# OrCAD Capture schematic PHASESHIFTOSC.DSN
size A
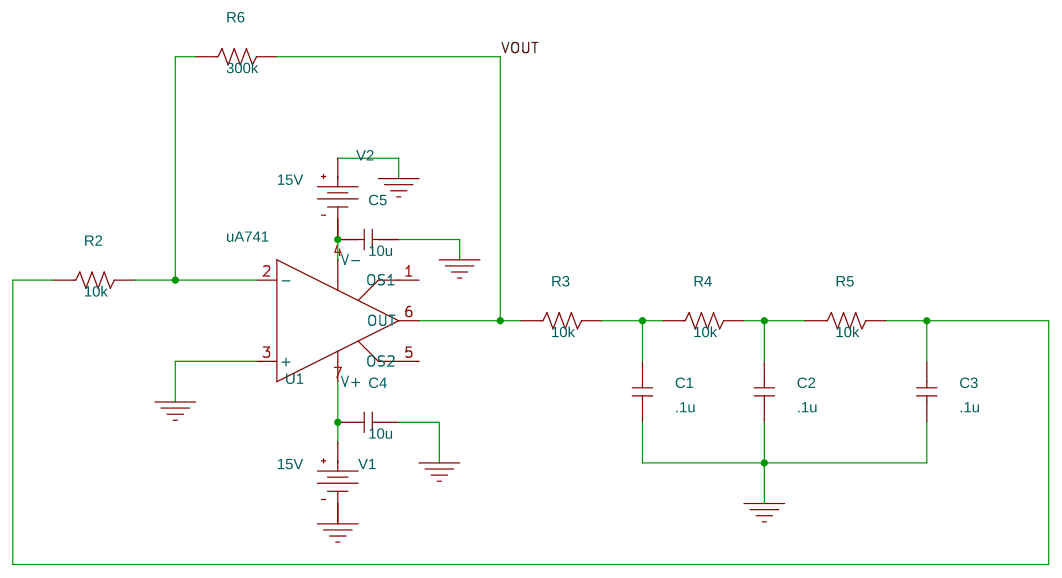
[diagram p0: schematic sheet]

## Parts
C1  .1u  [RAD/CK05]
C2  .1u  [RAD/CK05]
C3  .1u  [RAD/CK05]
C4  10u  [RAD/CK05]
C5  10u  [RAD/CK05]
R2  10k  [AX/RC05]
R3  10k  [AX/RC05]
R4  10k  [AX/RC05]
R5  10k  [AX/RC05]
R6  300k  [AX/RC05]
U1  uA741  [DIP.100/8/W.300/L.450]
V1  VDC
V2  VDC

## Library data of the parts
C1 C4 C5 = C: IC: 1
C2 C3 = C: IC: 0
R2-R6 = R
U1 = uA741
V1 V2 = VDC: DC: 15V

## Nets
0: C1.1 C2.1 C3.1 C4.2 C5.2 U1.3(+) V1.1(-) V2.0(+)
VOUT: R3.1 R6.2 U1.6(OUT)
N00380: C4.1 U1.7(V+) V1.0(+)
N00425: R2.2 R6.1 U1.2(-)
N00607: C1.2 R3.2 R4.1
N00620: C2.2 R4.2 R5.1
N00624: C3.2 R2.1 R5.2
N01822: C5.1 U1.4(V-) V2.1(-)

Not connected (* = marked no-connect by the designer): U1 1(OS1) 5(OS2)
